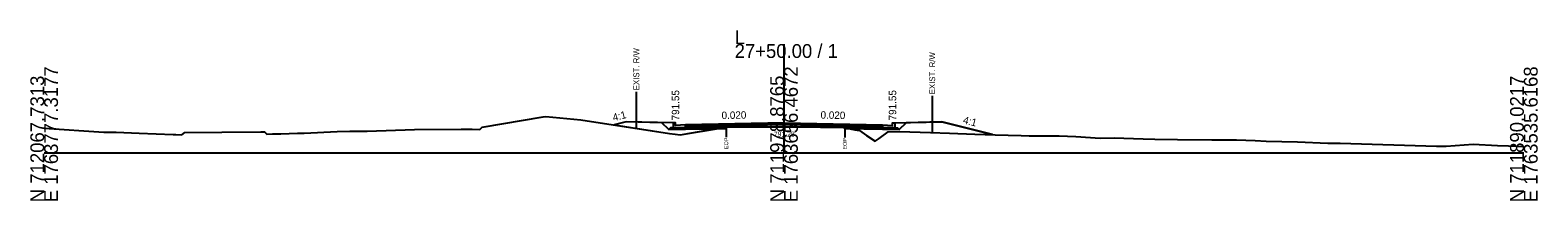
# Model space of a CAD drawing. Extents: x -26 to 5303, y -10 to 9578.
# Drawn here: x 997.2 to 1302.8, y 7490.3 to 7524.8 of the extents above; entities that cross this region are included whole.
import ezdxf

# ---------------------------------------------------------------- set-up
doc = ezdxf.new("R2010")
doc.units = 0
for name, color, linetype in [('Default', 7, 'Continuous'), ('Exist CMT Pavement', 7, 'Continuous'), ('Exist Cross Section Cell', 7, 'Continuous'), ('Exist XS Ground Line', 7, 'Continuous'), ('Old_Level_10', 7, 'Continuous'), ('Old_Level_3', 7, 'Continuous'), ('Prop CMT Conc Surface', 7, 'Continuous'), ('Prop CMT Concrete Structures', 7, 'Continuous'), ('Prop CMT Pvmt Course 1', 7, 'Continuous'), ('Prop CMT Pvmt Course 1 CG', 7, 'Continuous'), ('Prop CMT Pvmt Course 2', 7, 'Continuous'), ('Prop CMT Pvmt Course 3', 7, 'Continuous'), ('Prop CMT Pvmt Surface', 7, 'Continuous'), ('Prop CMT Slope Grass', 7, 'Continuous'), ('Prop CMT Subgrade Earthwork', 7, 'Continuous'), ('Prop XS Earthwork Shape', 7, 'Continuous'), ('Prop XS Hydro Elevations', 7, 'Continuous'), ('Prop XS SE Text', 7, 'Continuous'), ('Prop XS Side Slope Text', 7, 'Continuous'), ('Prop XS Wedging', 7, 'Continuous')]:
    doc.layers.add(name, color=color, linetype=linetype)

msp = doc.modelspace()

# ---------------------------------------------------------------- linework, layer by layer
at = {"layer": 'Exist CMT Pavement'}
msp.add_lwpolyline([(1138.3, 7505.22), (1138.3, 7505.22), (1139.11, 7505.23), (1139.52, 7505.23), (1140.96, 7505.26), (1141.77, 7505.27), (1144.06, 7505.27), (1145.99, 7505.28), (1146.67, 7505.28), (1147.17, 7505.28), (1148.46, 7505.28), (1148.89, 7505.28), (1150.15, 7505.28), (1150.65, 7505.28), (1151.37, 7505.27), (1152.03, 7505.26), (1153.37, 7505.25), (1154.43, 7505.24), (1156.48, 7505.23), (1157.4, 7505.21), (1158.65, 7505.21), (1159.19, 7505.2), (1159.58, 7505.2), (1161.18, 7505.16), (1162.01, 7505.14), (1162.32, 7505.12), (1162.32, 7505.12)], dxfattribs=at)
at = {"layer": 'Exist Cross Section Cell'}
for p, q in [((1150, 7500), (1150, 7521.98)), ((1000, 7500), (1150, 7500)), ((1150, 7500), (1300, 7500))]:
    msp.add_line(p, q, dxfattribs=at)
at = {"layer": 'Exist XS Ground Line'}
msp.add_lwpolyline([(1000, 7504.97), (1012.13, 7504.15), (1014.57, 7504.16), (1019.28, 7503.98), (1026.14, 7503.73), (1026.69, 7503.69), (1027.93, 7503.62), (1028.53, 7504.11), (1036.01, 7504.16), (1043.9, 7504.23), (1044.66, 7504.26), (1045.16, 7503.76), (1046.32, 7503.82), (1046.67, 7503.83), (1047.98, 7503.86), (1051.38, 7503.95), (1052.71, 7503.99), (1059.39, 7504.31), (1061.99, 7504.35), (1065.47, 7504.41), (1075.11, 7504.69), (1084.54, 7504.76), (1086.8, 7504.78), (1088.3, 7504.7), (1088.8, 7505.2), (1101.15, 7507.27), (1101.74, 7507.33), (1108.78, 7506.67), (1126.81, 7503.91), (1127.95, 7503.76), (1128.94, 7503.62), (1129.73, 7503.74), (1138.3, 7505.22), (1139.11, 7505.23), (1139.52, 7505.23), (1140.96, 7505.26), (1141.3, 7505.26), (1141.77, 7505.27), (1144.06, 7505.27), (1145.99, 7505.28), (1146.67, 7505.28), (1147.17, 7505.28), (1148.46, 7505.28), (1148.89, 7505.28), (1150.15, 7505.28), (1150.65, 7505.28), (1151.37, 7505.27), (1152.03, 7505.26), (1153.37, 7505.25), (1153.82, 7505.24), (1154.43, 7505.24), (1156.48, 7505.23), (1158.65, 7505.21), (1159.19, 7505.2), (1159.58, 7505.2), (1161.18, 7505.16), (1162.01, 7505.14), (1162.32, 7505.12), (1162.47, 7505.32), (1163.73, 7504.8), (1164.39, 7504.68), (1165.33, 7504.51), (1166.72, 7503.51), (1168.47, 7502.35), (1169.32, 7502.88), (1171.14, 7504.24), (1173.4, 7504.28), (1179.73, 7504.14), (1183.57, 7503.98), (1188.68, 7503.76), (1192.81, 7503.65), (1198.09, 7503.52), (1199.7, 7503.46), (1205.77, 7503.44), (1209.16, 7503.3), (1214.12, 7502.97), (1216.97, 7503.01), (1222.79, 7502.84), (1225.18, 7502.74), (1229.79, 7502.71), (1236.73, 7502.6), (1241.72, 7502.62), (1245.54, 7502.5), (1247.74, 7502.37), (1254.13, 7502.21), (1260.27, 7501.93), (1262.75, 7501.92), (1282.29, 7501.36), (1284.23, 7501.35), (1289.73, 7501.75), (1294.65, 7501.45), (1296.88, 7501.38), (1300, 7501.25)], dxfattribs=at)
at = {"layer": 'Old_Level_10'}
for p, q in [((1120.05, 7512.35), (1120.05, 7504.95)), ((1180.05, 7511.53), (1180.05, 7504.12)), ((1138.3, 7505.22), (1138.3, 7503.17)), ((1162.32, 7505.12), (1162.32, 7503.07))]:
    msp.add_line(p, q, dxfattribs=at)
at = {"layer": 'Prop CMT Conc Surface'}
for points in [[(1128, 7505.55), (1128, 7506.05), (1127.5, 7506.05)], [(1130, 7505.67), (1128, 7505.55)], [(1170, 7505.67), (1172, 7505.55)], [(1172, 7505.55), (1172, 7506.05), (1172.5, 7506.05)]]:
    msp.add_lwpolyline(points, dxfattribs=at)
at = {"layer": 'Prop CMT Concrete Structures'}
for points in [[(1130, 7505.67), (1128, 7505.55), (1128, 7506.05), (1127.5, 7506.05)], [(1127.5, 7506.05), (1127.5, 7505.04), (1130, 7505.09)], [(1130, 7505.09), (1130, 7505.67)], [(1170, 7505.67), (1172, 7505.55), (1172, 7506.05), (1172.5, 7506.05)], [(1172.5, 7506.05), (1172.5, 7505.04), (1170, 7505.09)], [(1170, 7505.09), (1170, 7505.67)]]:
    msp.add_lwpolyline(points, dxfattribs=at)
at = {"layer": 'Prop CMT Pvmt Course 1'}
for points in [[(1150, 7506.07), (1130, 7505.67)], [(1130, 7505.67), (1130, 7505.42)], [(1130, 7505.42), (1138.3, 7505.59)], [(1138.3, 7505.59), (1150, 7505.82)], [(1138.3, 7505.59), (1138.3, 7505.59)], [(1150, 7505.82), (1150, 7506.07)], [(1150, 7506.07), (1170, 7505.67)], [(1150, 7505.82), (1150, 7505.82), (1150, 7505.82)], [(1162.32, 7505.57), (1150, 7505.82)], [(1170, 7505.42), (1162.32, 7505.57)], [(1162.32, 7505.57), (1162.32, 7505.57)], [(1170, 7505.67), (1170, 7505.42)]]:
    msp.add_lwpolyline(points, dxfattribs=at)
at = {"layer": 'Prop CMT Pvmt Course 1 CG'}
for points in [[(1130, 7505.09), (1127, 7505.03), (1126.66, 7504.69)], [(1126.66, 7504.69), (1130, 7504.75)], [(1130, 7504.75), (1130, 7505.09)], [(1170, 7505.09), (1173, 7505.03), (1173.34, 7504.69)], [(1170, 7504.75), (1170, 7505.09)], [(1173.34, 7504.69), (1170, 7504.75)]]:
    msp.add_lwpolyline(points, dxfattribs=at)
at = {"layer": 'Prop CMT Pvmt Course 2'}
for points in [[(1138.3, 7505.59), (1130, 7505.42)], [(1130, 7505.42), (1130, 7505.09)], [(1130, 7505.09), (1138.3, 7505.25)], [(1138.3, 7505.25), (1138.3, 7505.59)], [(1162.32, 7505.24), (1162.32, 7505.57)], [(1162.32, 7505.57), (1170, 7505.42)], [(1170, 7505.09), (1162.32, 7505.24)], [(1170, 7505.42), (1170, 7505.09)]]:
    msp.add_lwpolyline(points, dxfattribs=at)
at = {"layer": 'Prop CMT Pvmt Course 3'}
for points in [[(1138.3, 7505.25), (1130, 7505.09)], [(1130, 7505.09), (1130, 7504.75)], [(1130, 7504.75), (1138.3, 7504.92)], [(1138.3, 7504.92), (1138.3, 7505.25)], [(1162.32, 7505.24), (1170, 7505.09)], [(1162.32, 7504.91), (1162.32, 7505.24)], [(1170, 7504.75), (1162.32, 7504.91)], [(1170, 7505.09), (1170, 7504.75)]]:
    msp.add_lwpolyline(points, dxfattribs=at)
at = {"layer": 'Prop CMT Pvmt Surface'}
for points in [[(1150, 7506.07), (1130, 7505.67)], [(1150, 7506.07), (1170, 7505.67)]]:
    msp.add_lwpolyline(points, dxfattribs=at)
at = {"layer": 'Prop CMT Slope Grass'}
for points in [[(1127.5, 7506.05), (1118, 7506.24), (1115.57, 7505.63)], [(1172.5, 7506.05), (1182, 7506.24), (1192.3, 7503.67)]]:
    msp.add_lwpolyline(points, dxfattribs=at)
at = {"layer": 'Prop CMT Subgrade Earthwork'}
for p, q in [((1138.3, 7505.22), (1138.3, 7504.92)), ((1162.32, 7505.12), (1162.32, 7504.91))]:
    msp.add_line(p, q, dxfattribs=at)
for points in [[(1130, 7504.75), (1126.66, 7504.69), (1125.25, 7506.09)], [(1138.3, 7504.92), (1130, 7504.75)], [(1162.32, 7504.91), (1170, 7504.75)], [(1170, 7504.75), (1173.34, 7504.69), (1174.75, 7506.09)]]:
    msp.add_lwpolyline(points, dxfattribs=at)
at = {"layer": 'Prop XS Earthwork Shape'}
for points in [[(1127.95, 7503.76), (1128.94, 7503.62), (1129.73, 7503.74), (1136.34, 7504.88), (1130, 7504.75), (1126.66, 7504.69), (1125.25, 7506.09), (1118, 7506.24), (1115.57, 7505.63), (1126.81, 7503.91)], [(1138.3, 7505.22), (1138.3, 7504.92), (1136.34, 7504.88)], [(1162.47, 7505.32), (1163.51, 7504.88), (1162.32, 7504.91), (1162.32, 7505.12)], [(1173.4, 7504.28), (1179.73, 7504.14), (1183.57, 7503.98), (1188.68, 7503.76), (1192.3, 7503.67), (1182, 7506.24), (1174.75, 7506.09), (1173.34, 7504.69), (1170, 7504.75), (1163.51, 7504.88), (1163.73, 7504.8), (1164.39, 7504.68), (1165.33, 7504.51), (1166.72, 7503.51), (1168.47, 7502.35), (1169.32, 7502.88), (1171.14, 7504.24)]]:
    msp.add_lwpolyline(points, close=True, dxfattribs=at)
at = {"layer": 'Prop XS Wedging'}
msp.add_lwpolyline([(1138.3, 7505.22), (1138.3, 7505.59), (1139.11, 7505.6), (1139.52, 7505.61), (1140.96, 7505.64), (1141.77, 7505.66), (1144.06, 7505.7), (1145.99, 7505.74), (1146.67, 7505.75), (1147.17, 7505.76), (1148.46, 7505.79), (1148.89, 7505.8), (1150, 7505.82), (1150.15, 7505.82), (1150.65, 7505.81), (1151.37, 7505.79), (1152.03, 7505.78), (1153.37, 7505.75), (1154.43, 7505.73), (1156.48, 7505.69), (1157.4, 7505.67), (1158.65, 7505.65), (1159.19, 7505.64), (1159.58, 7505.63), (1161.18, 7505.6), (1162.01, 7505.58), (1162.32, 7505.57), (1162.32, 7505.12), (1162.01, 7505.15), (1161.18, 7505.16), (1159.58, 7505.2), (1159.19, 7505.2), (1158.65, 7505.2), (1157.4, 7505.21), (1156.48, 7505.23), (1154.43, 7505.24), (1153.37, 7505.24), (1152.03, 7505.26), (1151.37, 7505.27), (1150.65, 7505.28), (1150.15, 7505.28), (1150, 7505.28), (1148.89, 7505.28), (1148.46, 7505.28), (1147.17, 7505.28), (1146.67, 7505.28), (1145.99, 7505.28), (1144.06, 7505.27), (1141.77, 7505.27), (1140.96, 7505.26), (1139.52, 7505.23), (1139.11, 7505.23)], close=True, dxfattribs=at)

# ---------------------------------------------------------------- texts
at = {"layer": 'Default'}
msp.add_text('-', height=0.0001, dxfattribs=at).set_placement((1000, 7500))
at = {"layer": 'Exist Cross Section Cell'}
for s, p in [('L', (1140, 7521.98)), ('27+50.00 / 1', (1140, 7519.18))]:
    msp.add_text(s, height=2.8, dxfattribs=at).set_placement(p)
for s, p in [('E 1763777.3177', (1002.8, 7490)), ('E 1763656.4672', (1152.8, 7490)), ('E 1763535.6168', (1302.8, 7490)), ('N 712067.7313', (1000, 7490)), ('N 711978.8765', (1150, 7490)), ('N 711890.0217', (1300, 7490))]:
    msp.add_text(s, height=2.8, rotation=90, dxfattribs=at).set_placement(p)
at = {"layer": 'Old_Level_10'}
for s, height, p in [('EXIST. R/W', 1.181, (1120.64, 7512.65)), ('EXIST. R/W', 1.181, (1180.64, 7511.83)), ('EOP', 0.787, (1138.69, 7500.77)), ('EOP', 0.787, (1162.72, 7500.67))]:
    msp.add_text(s, height=height, rotation=90, dxfattribs=at).set_placement(p)
at = {"layer": 'Old_Level_3'}
msp.add_text('791.28', height=1, dxfattribs=at).set_placement((1147.95, 7503.28))
at = {"layer": 'Prop XS Hydro Elevations'}
for p in [(1128.75, 7506.55), (1172.75, 7506.55)]:
    msp.add_text('791.55', height=1.5, rotation=90, dxfattribs=at).set_placement(p)
at = {"layer": 'Prop XS SE Text'}
for rotation, p in [(1.1458, (1137.36, 7506.82)), (358.8542, (1157.4, 7506.92))]:
    msp.add_text('0.020', height=1.5, rotation=rotation, dxfattribs=at).set_placement(p)
at = {"layer": 'Prop XS Side Slope Text'}
for rotation, p in [(14.0362, (1115.45, 7506.38)), (345.9638, (1186.18, 7505.97))]:
    msp.add_text('4:1', height=1.5, rotation=rotation, dxfattribs=at).set_placement(p)

doc.saveas('drawing.dxf')
